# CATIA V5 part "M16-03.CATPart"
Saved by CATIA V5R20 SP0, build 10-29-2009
Part number: M16-03
Revision: ANY
Definition: UNKNOWN
Nomenclature: M16-03
Source: Unknown
Bounding box of the stored display mesh (mm): x 0 to 50, y -17.5 to 17.5, z 0 to 20
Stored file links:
  C:\Users\Utente\Desktop\IO LAVORO\3D X SITO CF\X 3D SITO CF 27-09-2020\740T\M16-03.CATPart
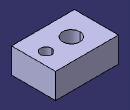
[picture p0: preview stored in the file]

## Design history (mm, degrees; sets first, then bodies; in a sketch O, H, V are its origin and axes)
Body1 "NONE" (main body)
  Solid1: solid without history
